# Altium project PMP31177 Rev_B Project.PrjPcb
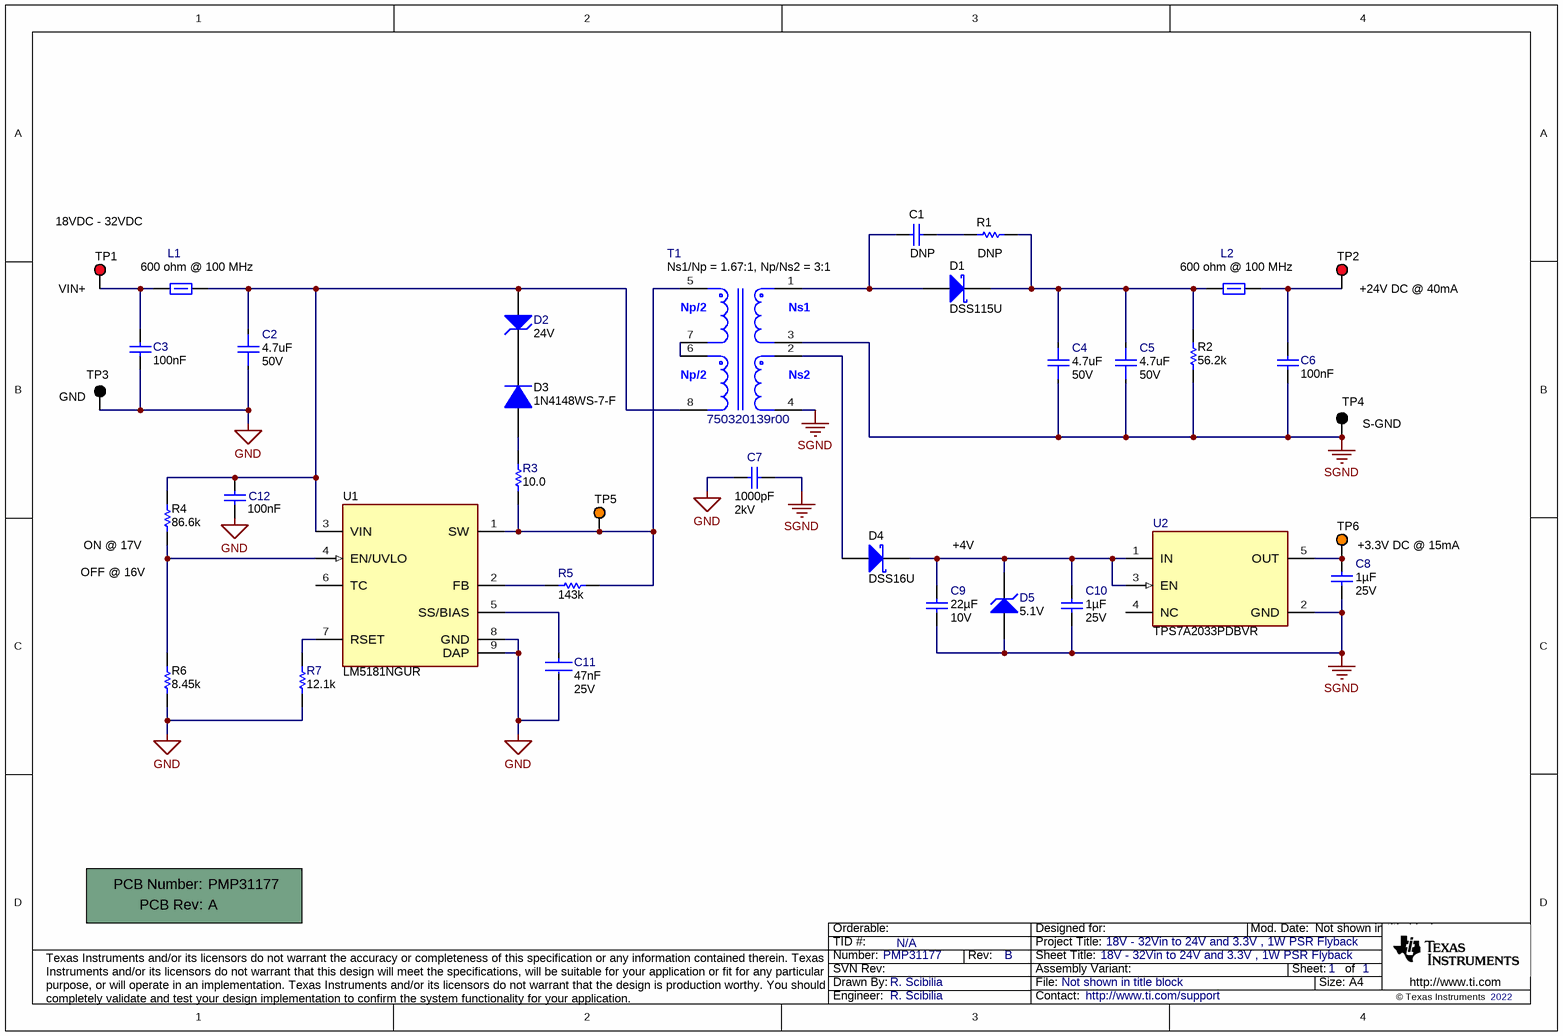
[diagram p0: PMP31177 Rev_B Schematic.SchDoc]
CopyrightYear: 2022; PCB_Rev: A; PRJ_Engineer: R. Scibilia; PRJ_Number: PMP31177; PRJ_Title: 18V - 32Vin to 24V and 3.3V , 1W PSR Flyback; SCH_Rev: B; TechSupport: http://www.ti.com/support; TID: N/A
1 sheet, 36 parts. Net scope: global (net labels, ports and power ports of the same name join across sheets).
Board file: PMP31177 Rev_A PCB.PcbDoc

## Sheet PMP31177 Rev_B Schematic.SchDoc: 18V - 32Vin to 24V and 3.3V , 1W PSR Flyback
size A4; Date: Not shown in title block; ApprovedBy: Not shown in title block; CheckedBy: Not shown in title block; Author: Not shown in title block; CompanyName: Not shown in title block; DrawnBy: R. Scibilia; Engineer: Not shown in title block; Organization: Not shown in title block; Address1: Not shown in title block; Address2: Not shown in title block; Address3: Not shown in title block; Address4: Not shown in title block; DocumentNumber: 1; Revision: Use project parameter SCH_Rev; SheetNumber: 1; SheetTotal: 1; PageSetup: Record=PageOptions¦CenterHorizontal=True¦CenterVertical=True¦PrintScale=1.00¦XCorrection=1.00¦YCorrection=1.00¦PrintKind=0¦BorderSize=5000000¦LeftOffset=0¦BottomOffset=0¦Orientation=2¦PaperLength=1000¦PaperWidth=1000¦Scale=100¦PaperSource=15¦PrintQuality=600¦MediaType=1¦DitherType=10¦PaperKind=Letter¦PrintScaleMode=1

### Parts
!PCB1  Printed Circuit Board  (value not drawn)  (mechanical)
C1  value DNP  [0603_HV]  (hidden comment: GRM1885C2A220JA01D)
C2  VDC_V: 50V  ValueDisplayed: 4.7uF  [FP-885012208094_1206-MFG]  (hidden comment: 885012208094)
C3  Cap_F: 100nF  [0603]  (hidden comment: 885012206120)
C4  VDC_V: 50V  ValueDisplayed: 4.7uF  [FP-885012208094_1206-MFG]  (hidden comment: 885012208094)
C5  VDC_V: 50V  ValueDisplayed: 4.7uF  [FP-885012208094_1206-MFG]  (hidden comment: 885012208094)
C6  Cap_F: 100nF  [0603]  (hidden comment: 885012206120)
C7  VDC_V: 2kV  ValueDisplayed: 1000pF  [1808]  (hidden comment: GR442QR73D102KW01L)
C8  Cap_F: 1µF  VDC_V: 25V  [0603]  (hidden comment: 885012206076)
C9  VDC_V: 10V  ValueDisplayed: 22µF  [0805_150]  (hidden comment: 885012107011)
C10  Cap_F: 1µF  VDC_V: 25V  [0603]  (hidden comment: 885012206076)
C11  Cap_F: 47nF  VDC_V: 25V  [FP-885012206069_0603-MFG]  (hidden comment: 885012206069)
C12  Cap_F: 100nF  [0603]  (hidden comment: 885012206120)
D1  DSS115U  [SOD-123FL]
D2  value 24V  [SOD-323]  (hidden comment: MMSZ5252BS-7-F)
D3  1N4148WS-7-F  [SOD-323]
D4  DSS16U  [SOD-123FL]
D5  value 5.1V  [SOD-323]  (hidden comment: BZT52C5V1S-7-F)
L1  value 600 ohm @ 100 MHz  [0805_HV]  (hidden comment: 74279220601)
L2  value 600 ohm @ 100 MHz  [0805_HV]  (hidden comment: 74279220601)
R1  value DNP  [0603L]  (hidden comment: CRCW0603100RFKEA)
R2  ValueDisplayed: 56.2k  [0603]  (hidden comment: RC0603FR-0756K2L)
R3  ValueDisplayed: 10.0  [0603]  (hidden comment: RC0603FR-0710RL)
R4  ValueDisplayed: 86.6k  [0603]  (hidden comment: RT0603DRE0786K6L)
R5  ValueDisplayed: 143k  [0603]  (hidden comment: RC0603FR-07143KL)
R6  ValueDisplayed: 8.45k  [0603]  (hidden comment: RC0603FR-078K45L)
R7  ValueDisplayed: 12.1k  [0603]  (hidden comment: RC0603FR-0712K1L)
T1  750320139r00  Ns1toNp: Ns1/Np = 1.67:1, Np/Ns2 = 3:1  [FP-750320139r00_SMT_TRANSFORMER_14MM00_10MM00-MFG]
TP1  5000  [Keystone5000]  (value not drawn)
TP2  5000  [Keystone5000]  (value not drawn)
TP3  5001  [Keystone5001]  (value not drawn)
TP4  5001  [Keystone5001]  (value not drawn)
TP5  5003  [Keystone5003]  (value not drawn)
TP6  5003  [Keystone5003]  (value not drawn)
U1  LM5181NGUR  [NGU0008C-MFG]
U2  TPS7A2033PDBVR  [DBV0005A-MFG]

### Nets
GND: C2.1 C3.2 C7.2 C11.2 C12.2 R6.1 R7.1 TP3.1 U1.8(GND) U1.9(DAP)
SGND: C4.1 C5.1 C6.2 C7.1 C8.2 C9.2 C10.2 D5.2(A) R2.1 T1.3 T1.4 TP4.1 U2.2(GND)
NetC1_1: C1.1 R1.2
NetC1_2: C1.2 D1.2(A) T1.1
NetC2_2: C2.2 C12.1 D2.2(A) L1.2 R4.2 T1.8 U1.3(VIN)
NetC3_1: C3.1 L1.1 TP1.1
NetC4_2: C4.2 C5.2 D1.1(K) L2.1 R1.1 R2.2
NetC6_1: C6.1 L2.2 TP2.1
NetC8_1: C8.1 TP6.1 U2.5(OUT)
NetC9_1: C9.1 C10.1 D4.1(K) D5.1(K) U2.1(IN) U2.3(EN)
NetC11_1: C11.1 U1.5(SS/BIAS)
NetD2_1: D2.1(K) D3.1(K)
NetD3_2: D3.2(A) R3.2
NetD4_2: D4.2(A) T1.2
NetR3_1: R3.1 R5.2 T1.5 TP5.1 U1.1(SW)
NetR4_1: R4.1 R6.2 U1.4(EN/UVLO)
NetR5_1: R5.1 U1.2(FB)
NetR7_2: R7.2 U1.7(RSET)
NetT1_6: T1.6 T1.7

Not connected (* = marked no-connect by the designer): U1 6(TC); U2 4(NC)

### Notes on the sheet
- 18VDC - 32VDC
- (near TP1) VIN+
- (near T1) Np/2
- (near T1) Ns1
- (near TP2) +24V DC @ 40mA
- (near T1) Ns2
- (near TP3) GND
- (near TP4) S-GND
- (near R4) ON @ 17V
- (near R4) OFF @ 16V
- +4V
- +3.3V DC @ 15mA

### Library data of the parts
!PCB1 = PCB: Manufacturer: Any; PartNumber: PMP31177 Rev_A PCB; SymbolCreator: a0412235
C1 = CMP-0007255-4: DNP; Polarized: N; SizeAreaWB_mm2: 4.68; U/M: EA; SizeZ_mm: 1; SizeX_mm: 1.6; SizeY_mm: 0.8; Cap_Case: 0603; SizeArea_mm2: 1.28; CompType: Capacitor; AEC Category: Q200
C2 C4 C5 = CMP-0088282-2: 4.7µF ±10% 50V Ceramic Capacitor X7R 1206 (3216 Metric); Manufacturer: Wurth Electronics; TempCo: 15%; Symbol Name: SYM-885012208094; SizeZ_mm: 1.9mm; AEC Qualified: No
C3 C6 C12 = CMP-0860985-1: CAP, CERM, 0.1 µF, 100 V,+/- 10%, X7R, 0603; Manufacturer: Wuerth; AEC Qualified: N; TaMin_C: -55°C; TaMax_C: 125°C; SizeY_mm: 0.8; ValueDisplayed: 0.1µF; SizeZ_mm: 1; Value2: 100V; U/M: EA; SizeAreaWB_mm2: 4.68; AEC Category: Q200; SizeArea_mm2: 1.28; Value: 0.1uF; SizeX_mm: 1.6
C7 = CMP-0009436-2: CAP, CERM, 1000 pF, 2000 V, +/- 10%, X7R, 1808; Manufacturer: MuRata; TaMin_C: -55°C; Polarized: N; SizeAreaWB_mm2: 16.5; Value1: Unknown; U/M: EA; Value: 1000pF; TaMax_C: 125°C; SizeZ_mm: 2.03; SizeX_mm: 4.5; SizeY_mm: 2; Value2: 2000V; SizeArea_mm2: 9; Cap_F: 1nF; AEC Category: Q200
C8 C10 = CMP-0006833-4: CAP, CERM, 1 uF, 25 V, +/- 10%, X7R, 0603; Manufacturer: Wurth Elektronik; TaMin_C: -55°C; Polarized: N; SizeAreaWB_mm2: 4.68; Value1: Unknown; U/M: EA; Value: 1uF; TaMax_C: 125°C; SizeZ_mm: 1; SizeX_mm: 1.6; SizeY_mm: 0.8; SizeArea_mm2: 1.28; AEC Category: Q200
C9 = CMP-0078153-1: CAP, CERM, 22 µF, 10 V,+/- 20%, X5R, 0805; Manufacturer: Wurth Elektronik; TaMin_C: -55°C; Polarized: N; SizeAreaWB_mm2: 6.75; U/M: EA; Value: 22uF; TaMax_C: 85°C; SizeZ_mm: 1.5; SizeX_mm: 2; SizeY_mm: 1.25; Cap_Case: 0805; SizeArea_mm2: 2.5; AEC Category: Q200
C11 = CMP-0086483-1: 0.047µF ±10% 25V Ceramic Capacitor X7R 0603 (1608 Metric); Manufacturer: Wurth Electronics; SizeZ_mm: 0.95mm; TempCo: 15%; Symbol Name: SYM-885012206069; AEC Qualified: No
D1 = CMP-0028776-1: Diode, Schottky, 150 V, 1 A, SOD-123FL; Manufacturer: SMC Diode Solutions; Io_A: 1A; Green_Lifecycle: Not Set; SizeAreaWB_mm2: 12.19; Vr_V: 150V; Green_REACh: Incomplete; TJmax_C: 150°C; U/M: EA; SizeZ_mm: 0.98; SizeX_mm: 3.6; SizeY_mm: 1.65; Vf_V: 940mV; Value2: 0.94V; SizeArea_mm2: 5.94; AEC Qualified: N; AEC Category: Q101
D2 = CMP-0005838-4: Diode, Zener, 24 V, 200 mW, SOD-323; Manufacturer: Diodes Inc.; SizeZ_mm: 1; SizeAreaWB_mm2: 8.695; AEC Category: Q101; Value1: 0.2W; RJA_CperW: 350; Power_W: 200mW; SizeArea_mm2: 3.645; SizeY_mm: 1.35; SizeX_mm: 2.7
D3 = CMP-0079597-2: Diode, Switching, 75 V, 0.15 A, AEC-Q101, SOD-323; Manufacturer: Diodes Inc.; SizeX_mm: 2.7; Vf_V: 1.25V; AEC Qualified: Y; SizeArea_mm2: 3.645; AEC Category: Q101; SizeAreaWB_mm2: 8.695; Io_A: 150mA; SizeZ_mm: 1; Value1: 0.15A; SizeY_mm: 1.35; TJmax_C: 150°C; Vr_V: 75V; Value: 75V
D4 = CMP-0028776-1: Diode, Schottky, 60 V, 1 A, SOD-123FL; Manufacturer: SMC Diode Solutions; Io_A: 1A; Green_Lifecycle: Not Set; SizeAreaWB_mm2: 12.19; Vr_V: 60V; Green_REACh: Incomplete; TJmax_C: 150°C; U/M: EA; SizeZ_mm: 0.98; SizeX_mm: 3.6; SizeY_mm: 1.65; Vf_V: 940mV; Value2: 0.94V; SizeArea_mm2: 5.94; AEC Qualified: N; AEC Category: Q101
D5 = CMP-0005865-3: Diode, Zener, 5.1 V, 200 mW, SOD-323; Manufacturer: Diodes Inc.; SizeY_mm: 1.35; SizeX_mm: 2.7; RJA_CperW: 625; AEC Category: Q101; SizeArea_mm2: 3.645; Value1: 0.2W; SizeZ_mm: 1; SizeAreaWB_mm2: 8.695; Power_W: 200mW
L1 L2 = CMP-0003136-1: Ferrite Bead, 600 ohm @ 100 MHz, 2.1 A, 0805; Manufacturer: Wurth Elektronik; Ztyp@1GHz_Ohm: 101.062; ZTyp@100MHz_Ohm: 600; SizeAreaWB_mm2: 6.75; DCR_ohm: 43m; Value1: 0.043 ohm; Imax_A: 2.1A; SizeZ_mm: 1.45; SizeX_mm: 2; SizeY_mm: 1.25; SizeArea_mm2: 2.5; ValueDisplayed: 600 ohm
R1 = CMP-0021991-3: DNP; U/M: EA; Res_ohm: 100; SizeX_mm: 1.6; SizeY_mm: 0.8; SizeZ_mm: 1; SizeArea_mm2: 1.28; CompType: Resistor; AEC Category: Q200
R2 = CMP-0023186-5: RES, 56.2 k, 1%, 0.1 W, 0603; Manufacturer: Yageo; Power_W: 100mW; TempCo: 100 ppm/C; Value_Code: 56k2; Value: 56.2k; EIA_Code: E96; SizeX_mm: 1.6; SizeY_mm: 0.8; SizeZ_mm: 1; Value2: 0.1W; SizeArea_mm2: 1.28; AEC Qualified: N; VDC_V: 75V; AEC Category: Q200; SizeAreaWB_mm2: 4.68
R3 = CMP-0022751-4: RES, 10.0, 1%, 0.1 W, 0603; Manufacturer: Yageo; Power_W: 100mW; TempCo: 100 ppm/C; Value_Code: 10R0; Value: 10.0; EIA_Code: E96; Res_ohm: 10; SizeX_mm: 1.6; SizeY_mm: 0.8; SizeZ_mm: 1; Value2: 0.1W; SizeArea_mm2: 1.28; AEC Qualified: N; VDC_V: 75V; AEC Category: Q200; SizeAreaWB_mm2: 4.68
R4 = CMP-0025613-3: RES, 86.6 k, 0.5%, 0.1 W, 0603; Manufacturer: Yageo America; Power_W: 100mW; TempCo: 50 ppm/C; Value_Code: 86k6; U/M: EA; Value: 86.6k; EIA_Code: E192; SizeX_mm: 1.6; SizeY_mm: 0.8; SizeZ_mm: 1; Value2: 0.1W; SizeArea_mm2: 1.28; VDC_V: 75V; AEC Category: Q200
R5 = CMP-0022798-4: RES, 143 k, 1%, 0.1 W, 0603; Manufacturer: Yageo; Power_W: 100mW; TempCo: 100 ppm/C; Value: 143k; EIA_Code: E96; SizeX_mm: 1.6; SizeY_mm: 0.8; SizeZ_mm: 1; Value2: 0.1W; SizeArea_mm2: 1.28; AEC Qualified: N; VDC_V: 75V; AEC Category: Q200; SizeAreaWB_mm2: 4.68
R6 = CMP-0023309-5: RES, 8.45 k, 1%, 0.1 W, 0603; Manufacturer: Yageo; Power_W: 100mW; TempCo: 100 ppm/C; Value_Code: 8k45; Value: 8.45k; EIA_Code: E96; SizeX_mm: 1.6; SizeY_mm: 0.8; SizeZ_mm: 1; Value2: 0.1W; SizeArea_mm2: 1.28; AEC Qualified: N; VDC_V: 75V; AEC Category: Q200; SizeAreaWB_mm2: 4.68
R7 = CMP-0022776-5: RES, 12.1 k, 1%, 0.1 W, 0603; Manufacturer: Yageo; Power_W: 100mW; TempCo: 100 ppm/C; Value_Code: 12k1; Value: 12.1k; EIA_Code: E96; SizeX_mm: 1.6; SizeY_mm: 0.8; SizeZ_mm: 1; Value2: 0.1W; SizeArea_mm2: 1.28; AEC Qualified: N; VDC_V: 75V; AEC Category: Q200; SizeAreaWB_mm2: 4.68
T1 = CMP-0095946-1: TRANSFORMER; Manufacturer: Wurth; DCR_ohm: 0.601; Voltage_Isolation_Vrms: 1.6kV; Frequency_Fixed: 350kHz; AEC Qualified: No; Ind_H: 77µH; SizeZ_mm: 5mm
TP1 TP2 = CMP-0055137-2: Test Point, Miniature, Red, TH; Manufacturer: Keystone Electronics; Green_REACh: Passed; Green_Lifecycle: Active; ContactFinish: Silver; CNHeader: FALSE; CT: TRUE
TP3 TP4 = CMP-0055138-2: Test Point, Miniature, Black, TH; Manufacturer: Keystone Electronics; ContactFinish: Silver; CNHeader: FALSE; Green_Lifecycle: Active; Green_REACh: Passed; CT: TRUE
TP5 TP6 = CMP-0055140-2: Test Point, Miniature, Orange, TH; Manufacturer: Keystone Electronics; Green_Lifecycle: Active; ContactFinish: Silver; CNHeader: FALSE; CT: TRUE; Green_REACh: Passed
U1 = CMP-0088992-1: 65-VIN PSR Flyback DC/DC Converter with 100-V, 0.75-A Integrated MOSFET; Manufacturer: Texas Instruments; SizeZ_mm: 0.8mm; TJmax_C: +150°C; Switching Frequency: 350kHz; Max Supply Voltage: 65V; Output Type: AdjustableProgrammable; Max Duty Cycle: 60%; Min Supply Voltage: 4.5V; AEC Qualified: No; Standoff Height: 0mm; Number Of Outputs: 1; Nominal Supply Current: 25-260uA
U2 = CMP-0092532-1: 300-mA, Ultra-Low-Noise, Low-IQ, High PSRR LDO; Manufacturer: Texas Instruments; TJmax_C: +125°C; Min Supply Voltage: 1.6V; SizeZ_mm: 1.45mm; Output Voltage: 3.3V; Number Of Outputs: 1; Nominal Supply Current: 6.5uA; AEC Qualified: No; Accuracy Percentage: 1.5%; Max Supply Voltage: 6V; Dropout Voltage: 145mV; Standoff Height: 0mm; Output Type: Fixed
